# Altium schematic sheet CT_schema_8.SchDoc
size 278 x 170 mm
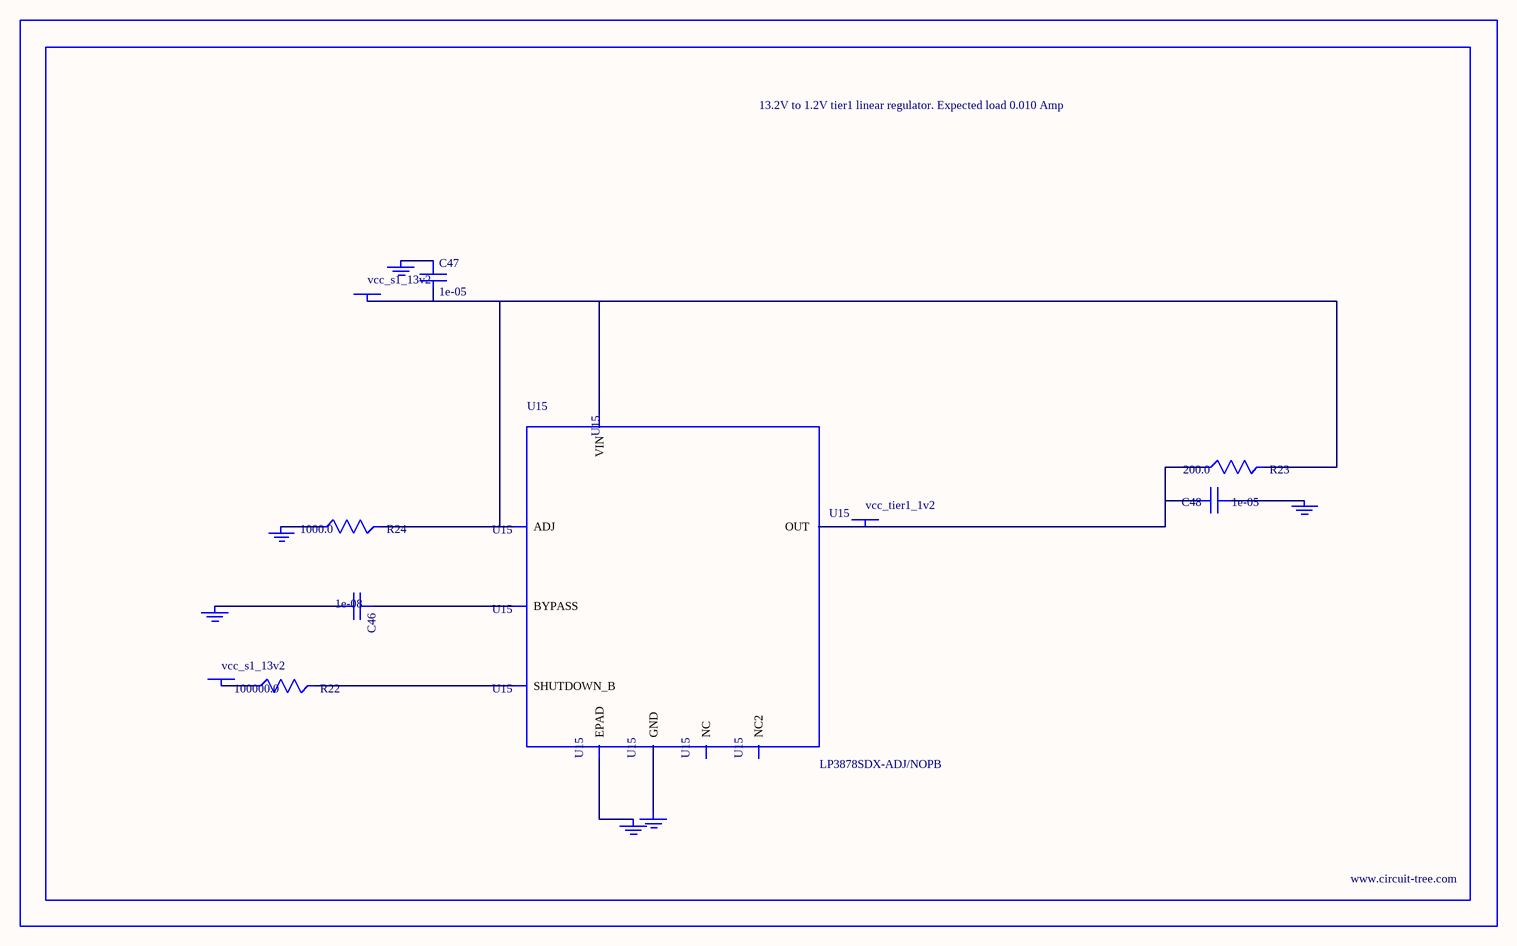
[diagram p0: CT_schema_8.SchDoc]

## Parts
BORDER7  (no value)
C46  1e-08  [C0402]
C47  1e-05  [C1210]
C48  1e-05  [C0805]
GND_INSTANCE_7_0  (no value)
GND_INSTANCE_7_1  (no value)
GND_INSTANCE_7_2  (no value)
GND_INSTANCE_7_3  (no value)
GND_INSTANCE_7_4  (no value)
GND_INSTANCE_7_5  (no value)
POWER_INSTANCE_7_0  vcc_s1_13v2
POWER_INSTANCE_7_1  vcc_s1_13v2
POWER_INSTANCE_7_2  vcc_tier1_1v2
R22  100000.0  [R0603]
R23  200.0  [R0603]
R24  1000.0  [R0603]
U15  LP3878SDX-ADJ/NOPB  [WSON-8]

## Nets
NetC46_1: C46.1 U15.1(BYPASS)
NetC46_2: C46.2 GND_INSTANCE_7_0.0(GND)
NetC47_1: C47.1 GND_INSTANCE_7_1.0(GND)
NetC47_2: C47.2 POWER_INSTANCE_7_0.0(PWR) R23.2 R24.2 U15.4(VIN) U15.6(ADJ)
NetC48_1: C48.1 GND_INSTANCE_7_2.0(GND)
NetC48_2: C48.2 POWER_INSTANCE_7_2.0(PWR) R23.1 U15.5(OUT)
NetGND_INSTANCE_7_3_0: GND_INSTANCE_7_3.0(GND) R24.1
NetGND_INSTANCE_7_4_0: GND_INSTANCE_7_4.0(GND) U15.PAD(EPAD)
NetGND_INSTANCE_7_5_0: GND_INSTANCE_7_5.0(GND) U15.3(GND)
NetPOWER_INSTANCE_7_1_0: POWER_INSTANCE_7_1.0(PWR) R22.1
NetR22_2: R22.2 U15.8(SHUTDOWN_B)

Not connected (* = marked no-connect by the designer): U15 2(NC) 7(NC2)

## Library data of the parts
BORDER7 = BORDER_PAGE7
C46 = C0402C103K3RAC
C47 = C1210C106K5PACTU
C48 = GRM219R60J106ME19D
GND_INSTANCE_7_0-GND_INSTANCE_7_5 = GND
POWER_INSTANCE_7_0-POWER_INSTANCE_7_2 = PWR
R22 = RC0603JR-07100KL
R23 = RC0603JR-07200RL
R24 = RC0603JR-071KL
